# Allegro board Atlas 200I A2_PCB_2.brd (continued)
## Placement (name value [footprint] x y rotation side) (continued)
C3530  1nF  [SC0402-PA]  32.51 112.27 0 top
C3531  1nF  [SC0402-PA]  32.51 111.25 0 top
C3532  1nF  [SC0402-PA]  32.51 109.22 0 top
C3601  10nF  [SC0402-PB]  54.48 16.13 0 top
C3602  10nF  [SC0402-PB]  51.56 16.13 180 top
C3603  10nF  [SC0402-PB]  43.49 6.98 270 top
C3604  100nF  [SC0402-PB]  54.1 22.73 180 top
C3605  100nF  [SC0402-PB]  50.8 22.73 180 top
C3606  100nF  [SC0603-TC]  62.48 6.73 180 top
C3607  100nF  [SC0603-TC]  70.87 8.64 90 top
C3610  1nF  [SC0402-PA]  73.2 11.61 270 top
C3611  10nF  [SC0402-PB]  60.96 16.13 0 top
C3612  10nF  [SC0402-PB]  58.04 16.13 180 top
C3613  10nF  [SC0402-PB]  53.09 6.73 270 top
C3614  100nF  [SC0402-PB]  61.6 22.86 180 top
C3615  100nF  [SC0402-PB]  57.91 22.86 180 top
C3616  100nF  [SC0402-PB]  37.94 19.67 90 top
C3617  100nF  [SC0402-PB]  18.42 27.18 0 top
D1  LED  [HSD0603-LED]  134.57 84.58 180 top
D2  D2-3_D  [SOT23]  25.91 141.33 90 top
D3  D2-3_D*  [SOT23]  11.38 157.73 0 top
D4  DZ_A  [HSOD523]  168.45 84.96 90 top
D5  D_A  [SD2211]  32.43 167.94 90 top
D6  NONE  [SD3-2618C]  42.01 86.96 90 top
D7  D2-3_D  [SOT23]  146.05 9.91 180 top
D8  D2-3_D  [SOT23]  218.14 169.67 0 top
D9  D2-3_D  [SOT23]  163.2 21.08 270 top
D10  NONE  [SOP8-50-173]  144.76 170.07 180 top
D11  NONE  [SOP8-50-173]  162.18 170.07 0 top
D12  NONE  [SOP8-50-173]  174.65 169 0 top
D13  NONE  [SOP8-50-173]  206.11 170.37 0 top
D14  NONE  [SOP8-50-173]  224.27 170.37 180 top
D15  SCHOKITTY-041-70V  [SOT23]  61.77 38.99 180 top
D16  D2-3_D  [SOT23D]  210.74 195.58 180 top
D17  D2-3_D  [SOT23D]  214.12 195.58 180 top
D18  D_A  [SD1107S]  73.69 15.12 180 top
D19  D_A  [SD1107S]  73.69 17.4 180 top
D701  LED  [HSD0603-LED]  4.47 147.19 90 top
D801  LED  [HSD0603-LED]  194.03 80.04 180 top
D1101  D_A  [SD1107S]  229.24 49.4 270 top
D1102  D_A  [SD1107S]  229.24 42.54 270 top
D1501  NONE  [SOP8-50-173]  212.36 170.37 180 top
D1502  NONE  [SOP8-50-173]  180.36 169 180 top
D1503  NONE  [SOP8-50-173]  168.26 170.07 180 top
D1504  NONE  [SOP8-50-173]  151.01 170.07 180 top
D1601  NONE  [SOP8-50-173]  230.89 170.37 180 top
D1701  NONE  [SOT23]  67.44 162.88 0 top
D1702  NONE  [SOT23]  86.44 199.41 180 top
D1703  NONE  [SD1814C]  44.96 179.96 270 top
D1704  NONE  [SD1814C]  40.51 179.96 270 top
D1705  NONE  [SD1814C]  49.4 179.96 270 top
D1706  NONE  [SD1814C]  53.85 180.01 270 top
D1707  NONE  [SD1814C]  67.18 180.01 270 top
D1708  NONE  [SD1814C]  71.63 180.01 270 top
D1709  NONE  [SD1814C]  58.29 180.01 270 top
D1710  NONE  [SD1814C]  62.74 180.01 270 top
D1711  NONE  [SD1814C]  74.35 186.56 0 top
D1712  NONE  [SD1814C]  67.18 194.58 90 top
D1713  NONE  [SD1814C]  62.74 194.58 90 top
D1714  NONE  [SD1814C]  76.07 180.01 270 top
D1715  NONE  [SD1814C]  62.74 187.19 90 top
D1716  NONE  [SD1814C]  58.29 194.58 90 top
D1717  NONE  [SD1814C]  53.85 194.58 90 top
D1718  NONE  [SD1814C]  58.29 187.19 90 top
D1719  NONE  [SD1814C]  49.4 194.58 90 top
D1720  NONE  [SD1814C]  49.4 187.19 90 top
D1721  NONE  [SD1814C]  53.85 187.19 90 top
D1722  NONE  [SD1814C]  42.49 186.36 0 top
D1723  NONE  [SOT23]  53.47 162.88 0 top
D1724  NONE  [SOT23]  44.07 162.88 0 top
D1725  NONE  [SOT23]  60.58 162.88 0 top
D2201  NONE  [MLF10B-050-0301L]  207.03 154 90 top
D2202  NONE  [MLF10B-050-0301L]  156.34 18.57 270 top
D2203  NONE  [MLF10B-050-0301L]  167.56 19.45 180 top
D2303  NONE  [MLF10B-050-0301L]  102.57 198.35 180 top
D2305  NONE  [MLF10B-050-0301L]  107.52 198.35 180 top
D2307  NONE  [SOT23]  124.71 198.7 180 top
D2403  NONE  [MLF10B-050-0301L]  90.3 199.85 180 top
D2405  NONE  [MLF10B-050-0301L]  93.55 199.85 180 top
D2407  NONE  [SOT23]  97.66 192.02 90 top
D2408  NONE  [SOT23]  108.94 188.39 90 top
D2501  D2-3_D  [SOT23]  201.5 16.87 270 top
D2502  D2-3_D  [SOT23]  192.25 16.67 0 top
D2503  D2-3_D  [SOT23]  205.97 16.64 270 top
D2504  D2-3_D  [SOT23]  213.13 16 180 top
D3001  NONE  [SD1710A]  14.05 188.92 0 top
D3301  D2-3_D  [SOT23]  185.8 28.57 180 top
D3302  D2-3_D  [SOT23D]  223.65 22.99 270 top
D3401  D_A  [SD1107S]  9.98 47.5 270 top
D3402  NONE  [SD1814C]  44.96 18.54 0 top
D3501  NONE  [SD3-2618C]  36.2 134.24 180 top
D3502  NONE  [SD3-2618C]  28.7 111.23 180 top
D3601  NONE  [SD1814C]  31.88 18.8 180 top
D3602  NONE  [SD1814C]  24.69 18.8 0 top
F1001  NONE  [SF2-0302A]  188.1 56.83 90 top
F3001  NONE  [SF6127]  21.44 189.08 180 top
F3002  NONE  [SF2-0302A]  17.15 161.54 180 top
F3301  NONE  [SF6127]  185.17 35.13 270 top
F3302  NONE  [SF6127]  212.34 25.78 0 top
F3501  NONE  [SF6127]  34.67 154.43 0 top
F3502  NONE  [SF6127]  31.27 142.01 270 top
ICT1  NONE  [HOLE125]  5.44 71.14 0 top
ICT2  NONE  [HOLE125]  225.53 144.98 0 top
ID1  NONE  [ID-BOARD]  7.37 40.54 180 bottom
ID2  NONE  [ID-BOARD]  2.21 193.88 0 top
ID3  NONE  [ID-BOARD]  237.49 8.25 180 bottom
ID4  NONE  [ID-BOARD]  226.14 156.31 0 top
ID5  NONE  [ID-BOARD]  237.49 8.25 0 top
ID6  NONE  [ID-BOARD]  226.16 156.31 180 bottom
ID7  NONE  [ID-BOARD]  5.72 65.79 0 top
ID8  NONE  [ID-BOARD]  4.27 193.6 180 bottom
J1  NONE  [COPPER0201]  168.82 61.29 180 top
J2  NONE  [PPWC0304-RF]  12.7 200.58 180 top
J3  NONE  [SDIM02161-20B]  88.6 121.95 0 top
J4  NONE  [MOUNT3-2009F]  221.05 12.5 270 top
J5  NONE  [MOUNT3-2009F]  239.25 198.9 90 top
J7  NONE  [MOUNT3-2009F]  4.25 12.5 270 top
J8  NONE  [MB1-1612]  16.77 63.25 90 top
J9  NONE  [MB1-1612]  16.77 101.25 90 top
J601  NONE  [CARD75-2207]  16.76 149.35 0 top
J701  NONE  [SDIM0226-32]  150.75 92 0 top
J702  NONE  [SSIM0107-50-1927]  101.55 15.6 0 top
J803  NONE  [CARD75-2208B]  183.28 91.87 180 top
J901  NONE  [PIDC36-DRF-C]  243.05 14.87 90 top
J902  NONE  [RWBC0202-165R-A]  242.73 32.1 90 top
J903  NONE  [PMR0203-165RQ-A]  238.61 49.1 90 top
J1501  NONE  [MJ2-0102SRL-A]  158.11 203.35 180 top
J1502  NONE  [MJ2-0102SRL-A]  193.12 203.35 180 top
J1601  NONE  [MJ2-0102SRL-A]  228.12 203.35 180 top
J1701  NONE  [TB14-138S]  58.34 206.15 180 top
J1702  NONE  [TB10-138S-A]  78.16 206.15 180 top
J1901  NONE  [HSDC10-1614B]  123.08 11 0 top
J2001  NONE  [COPPER0201]  176.1 65.99 180 top
J2201  NONE  [RUSB9-200-1417A]  178.5 6.73 0 top
J2202  NONE  [RUSB9-200-1417A]  157.5 6.73 0 top
J2203  NONE  [RUSB9-180-0726J]  217.64 151.83 0 top
J2301  NONE  [RUSB19-050-1512]  117.95 208.6 180 top
J2401  NONE  [RUSB19-050-1512]  93.75 208.61 180 top
J2501  NONE  [VAF6-1406E]  195.7 4.15 90 top
J2502  NONE  [VAF6-1406E]  208.7 4.15 90 top
J2701  NONE  [SED40-32M-H]  34.39 34.59 0 top
JP960  *  [RHOLE168-T244B188]  183.28 143.65 0 top
K1701  NONE  [SRLY8-87-224]  67.92 170.61 90 top
K1702  NONE  [SRLY8-87-224]  48.66 170.61 90 top
K1703  NONE  [SRLY8-87-224]  38.78 170.61 90 top
K1704  NONE  [SRLY8-87-224]  58.29 170.61 90 top
L1001  110nH  [SL0806B]  186.84 70.81 270 top
L1201  2.2uH  [SL0806A]  145.01 65.43 180 top
L1401  1uH  [SL1008H]  102.77 149.55 90 top
L2001  4.7uH*  [SPL0302E]  131.95 35.13 270 top
L2101  4.7uH  [SPL0302E]  124.74 39.04 270 top
L3001  1uH  [SPL0707N]  8.76 163.7 0 top
L3101  1uH  [SPL0707N]  99.85 156.57 180 top
L3102  2.2uH  [SPL0404L]  98.98 176.2 270 top
L3103  2.2uH  [SPL0404L]  116.87 173.94 0 top
L3104  110nH  [SL0806B]  105.58 182.45 0 top
LB1  NONE  [SL0402C]  204.22 30.73 270 top
LB2  NONE  [SL0402C]  137.67 184.78 90 top
LB3  NONE  [SL0402C]  21.61 117.38 0 top
LB4  NONE  [SL0402C]  9.87 115.53 90 top
LB5  NONE  [SL0402C]  20.77 138.97 90 top
LB6  NONE  [SL0402C]  20.18 137.64 180 top
LB7  NONE  [SL0402C]  16.32 116.33 90 top
LB8  NONE  [SL0402C]  92.96 154.94 90 top
LB9  *  [SL0402C]  90.68 154.94 90 top
LB10  NONE  [SL0402C]  93.98 167 180 top
LB401  NONE  [SL0402C]  14.03 138.44 0 top
LB402  NONE  [SL0402C]  4.52 115.23 180 top
LB403  NONE  [SL0402C]  18.86 116.84 180 top
LB404  NONE  [SL0402C]  8.16 113.31 90 top
LB405  NONE  [SL0402C]  10.77 140.29 0 top
LB406  NONE  [SL0402C]  10.77 139.15 0 top
LB702  NONE  [SL0805]  157.02 77.14 0 top
LB703  NONE  [SL0805]  157.02 78.71 0 top
LB802  *  [SL0402C]  182.4 77.77 90 top
LB1202  NONE  [SL0402C]  142.9 63.45 270 top
LB1203  NONE  [SL0402C]  154.84 68.33 90 top
LB1401  NONE  [SL0402C]  104.8 145.69 180 top
LB1402  NONE  [SL0402C]  109.45 153.87 90 top
LB1403  NONE  [SL0402C]  110.74 155.98 0 top
LB1404  NONE  [SL0402C]  106.53 156.34 270 top
LB1405  NONE  [SL0402C]  110.26 151.71 0 top
LB1406  NONE  [SL0402C]  117.27 134.13 90 top
LB1407  NONE  [SL0402C]  109.14 143.85 0 top
LB1601  NONE  [SL0805-TD]  75.03 170.08 90 top
LB1602  NONE  [SL0805-TD]  76.78 170.08 90 top
LB1603  NONE  [SL0805]  216.92 183.46 90 top
LB1604  NONE  [SL0805]  218.49 183.46 90 top
LB1605  NONE  [SL0805]  80.02 170.08 90 top
LB1606  NONE  [SL0805]  78.44 170.08 90 top
LB1607  NONE  [SL0805]  83.17 170.08 90 top
LB1608  NONE  [SL0805]  81.59 170.08 90 top
LB1610  NONE  [SL0805]  187.12 159.46 180 top
LB1701  NONE  [SL0805]  70.99 162.56 180 top
LB1702  NONE  [SL0805]  83.46 198.25 270 top
LB1703  NONE  [SL0805]  57.02 162.56 180 top
LB1704  NONE  [SL0805]  47.24 161.8 90 top
LB1705  NONE  [SL0805]  64.01 162.56 180 top
LB2001  *  [SL0805]  145.42 54.99 270 top
LB2002  *  [SL0402C]  131.32 49.17 180 top
LB2101  NONE  [SL0805]  109.47 33.65 0 top
LB2201  NONE  [SL0402C]  155.4 30.4 0 top
LB2202  NONE  [SL0402C]  141.84 24.41 270 top
LB2203  NONE  [SL0402C]  234.09 174.09 270 top
LB2501  *  [SL0805]  188.85 4.83 0 top
LB2502  NONE  [SL0805]  200.14 13.24 90 top
LB2503  NONE  [SL0805]  192.41 13.73 0 top
LB2504  NONE  [SL0805]  187.58 2.41 180 top
LB2505  NONE  [SL0805]  192.08 24.21 180 top
LB2506  *  [SL0805]  209.17 12.57 180 top
LB2507  NONE  [SL0805]  212.42 12.57 0 top
LB2508  NONE  [SL0805]  203.96 13.59 180 top
LB2509  NONE  [SL0805]  214.91 12.52 90 top
LB2801  NONE  [SL0402C]  205.74 30.35 0 top
LB3001  NONE  [SL0402C]  8 138.58 0 top
LB3601  NONE  [SL0805]  43.15 10.16 90 top
LB3602  NONE  [SL0805]  62.48 8.89 90 top
LB3603  NONE  [SL0805]  53.09 9.78 90 top
LED3601  NONE  [SDA4-0606]  66.9 6.96 0 top
LED3602  NONE  [SDA4-0606]  46.89 6.96 0 top
LED3603  NONE  [SDA4-0606]  56.9 6.96 0 top
M1  NONE  [HOLE138-M3]  33.5 56.3 0 top
M2  NONE  [HOLE138-M3]  67 29.55 0 top
M3  NONE  [HOLE138-M3]  213.6 33.9 0 top
M4  NONE  [HOLE138-M3]  176 78.3 0 top
M5  NONE  [HOLE138-M3]  115 194.8 0 top
M6  NONE  [HOLE138-M3]  31 184 0 top
M7  NONE  [HOLE138-M3]  193.68 189.04 0 top
M8  NONE  [WSA1-1405]  192.7 170.8 0 top
M9  NONE  [WSA1-1405]  129.9 177.7 0 top
M10  NONE  [RHOLE168-T244B188B]  51.6 34.6 0 top
M11  NONE  [RHOLE168-T244B188B]  17.2 34.6 0 top
M12  NONE  [HOLE168-T244B188]  34.4 43.9 0 top
M13  none  [HOLE130]  200.5 32 0 top
M14  none  [HOLE138E]  21.7 170.8 0 top
M15  NONE  [HOLE138-M3]  150.75 119.65 0 top
M16  NONE  [HOLE197-315]  138.65 140.05 0 top
M17  NONE  [HOLE197-315]  162.85 140.05 0 top
M18  NONE  [HOLE78]  33.4 205 0 top
M19  NONE  [RHOLE189-254]  126.35 110.3 0 top
M20  NONE  [RHOLE189-254]  50.85 110.3 0 top
M21  NONE  [RHOLE189-254]  50.85 66.3 0 top
M22  NONE  [RHOLE189-254]  126.35 66.3 0 top
M23  NONE  [HOLE138-M3]  75.4 196.25 0 top
M24  NONE  [HOLE138-M3]  40.6 196.25 0 top
M25  NONE  [HOLE78]  82.6 208.02 0 top
M26  NONE  [HOLE177]  85.59 107.57 0 top
M27  NONE  [HOLE138-M3]  181.4 104.65 0 top
M28  NONE  [HOLE138-M3]  181.4 132.65 0 top
M3601  NONE  [LG2-1705]  66.9 12.4 270 top
M3602  NONE  [LG2-1705]  46.9 12.4 270 top
M3603  NONE  [LG2-1705]  56.9 12.4 270 top
NOREF  -  []  -254 -254 0 top
NOREF#2  -  [unnamed#2]  100.85 88.3 270 top
NOREF#3  -  [unnamed#2]  242.96 53.96 180 top
NOREF#4  -  []  49.35 72.21 0 top
NOREF#5  -  [unnamed#2]  201.4 129.26 90 top
NOREF#6  -  []  119.38 297.52 0 top
NOREF#7  -  []  66.42 0 90 top
NOREF#8  -  []  -254 -254 0 top
NOREF#9  -  []  -254 -254 0 top
NOREF#10  -  []  83.44 17.4 270 top
NOREF#11  -  []  151.11 160.93 0 top
NOREF#12  -  []  -254 -254 0 top
NOREF#13  -  [unnamed#2]  75.1 103.3 180 top
NOREF#14  -  []  84.71 368.13 0 top
NOREF#15  -  [unnamed#2]  231.5 151.15 90 top
NOREF#16  -  [unnamed#2]  201.4 87.14 90 top
NOREF#17  -  []  166.32 150.57 0 top
NOREF#18  -  []  246.38 7.62 0 top
NOREF#19  -  [unnamed#2]  75.1 73.3 180 top
NOREF#20  -  []  -254 -254 0 top
NOREF#21  -  [unnamed#2]  214.39 61.26 180 top
NOREF#22  -  [unnamed#2]  49.35 88.3 270 top
NOREF#23  -  []  3.23 82.37 0 top
NOREF#24  -  []  0 199.38 0 top
NOREF#25  -  []  7.09 81.94 90 top
NOREF#26  -  []  13.67 68.78 0 top
NOREF#27  -  []  -104.14 -189.23 0 top
NOREF#28  -  []  238.76 189.23 0 top
NOREF#29  -  []  137.57 164.76 0 top
NOREF#30  -  [unnamed#2]  241.92 181.48 90 top
NOREF#31  -  []  13.67 108 0 top
NOREF#32  -  []  5.31 21.89 0 top
Q1  FETN-GSD*  [SOT23]  76.71 130.49 270 top
Q2  FETN-GSD  [SOT23]  65.18 20.07 180 top
Q3  PMOS-GSD  [SOT23-3]  59.41 27.73 180 top
Q4  FETN-GSD  [SOT23]  10.67 26.92 0 top
Q701  FETN-GSD  [SOT523-3A]  189.84 67.79 90 top
Q702  NPN-BEC  [SOT23]  190.34 62.79 0 top
Q801  NPN-BEC  [SOT23]  189.15 76.02 90 top
Q1001  FETN-GSD  [SOT523-3A]  173.74 57.68 180 top
Q1002  FETN-GSD  [SOT523-3A]  176.28 54.97 270 top
Q1003  NPN-BEC  [SOT23]  166.7 72.34 0 top
Q1004  FETN-GSD  [SOT523-3A]  171.32 72.34 0 top
Q1101  MOS_SGD  [RF8-FSC-FDMS86181]  223.67 51.05 0 top
Q1102  MOS_SGD  [RF8-FSC-FDMS86181]  216.31 43.31 0 top
Q1103  MOS_SGD  [RF8-FSC-FDMS86181]  216.31 51.05 0 top
Q1104  MOS_SGD  [RF8-FSC-FDMS86181]  223.67 43.31 0 top
Q1105  FETN-GSD  [SOT523-3A]  223.01 56.51 90 top
Q1106  FETN-GSD  [SOT523-3A]  211.2 55.12 270 top
Q1107  NPN-BEC  [SOT23]  213.87 56.51 90 top
Q1701  NPN-BEC  [SOT23]  67.44 158.75 0 top
Q1702  NPN-BEC  [SOT23]  49.89 162.88 0 top
Q1703  NPN-BEC  [SOT23]  40.51 162.88 0 top
Q1704  NPN-BEC  [SOT23]  60.58 158.95 0 top
Q1801  PMOS-GSD  [SOT23-3]  33.78 159.26 270 top
Q1802  PMOS-GSD  [SOT23-3]  36.32 162.43 270 top
Q1803  NPN-BEC  [SOT23]  25.5 157.99 270 top
Q1804  NPN-BEC  [SOT23]  30.15 161.47 270 top
Q1901  PMOS-GSD  [SOT23-3]  132.19 13.19 90 top
Q1902  NPN-BEC  [SOT23]  133.95 6.38 90 top
Q2101  FETN-GSD  [SOT523-3A]  58.98 40.28 0 top
Q2901  NPN-BEC  [SOT23]  25.53 134.06 270 top
Q3001  MOS_SGD  [RF8-NXP-PSMN1R0]  10.41 176.78 0 top
Q3101  FETN-GSD  [SOT523-3A]  154 64.74 270 top
Q3102  PMOS-SGD  [RF8-TOS-TPCC8105]  152.25 58.24 180 top
Q3103  FETN-GSD  [SOT523-3A]  111.3 175.49 90 top
Q3104  FETN-GSD  [SOT523-3A]  112.81 187.67 90 top
Q3105  NPN-BEC  [SOT23]  109.42 169.44 90 top
Q3106  NPN-BEC  [SOT23]  116.21 184.28 90 top
Q3201  FETN-GSD  [SOT523-3A]  157.66 61.77 180 top
Q3202  PMOS-SGD  [RF8-TOS-TPCC8105]  157.42 55.9 180 top
Q3301  PMOS-SGD  [SOT-PPAK-8-0303G]  218.97 24.36 270 top
Q3302  FETN-GSD  [SOT523-3A]  213.74 20.19 270 top
Q3303  PMOS-SGD  [SOT-PPAK-8-0303G]  181.99 28.63 180 top
Q3304  NPN-BEC  [SOT23]  178.82 36.78 270 top
Q3401  NPN-BEC  [SOT23]  17.45 83.9 180 top
Q3402  NPN-BEC  [SOT23]  21.06 83.9 180 top
Q3501  PMOS-SGD  [SOT-PPAK-8-0303G]  37.23 148.3 180 top
Q3502  NPN-BEC  [SOT23]  32.06 148.21 270 top
Q3503  NPN-BEC  [SOT23]  25.53 137.69 270 top
Q3504  PMOS-SGD  [RF8-TOS-TPCC8105]  31.52 134.17 180 top
Q3601  NPN-BEC  [SOT23]  53.98 20.07 180 top
Q3602  NPN-BEC  [SOT23]  50.29 20.07 180 top
Q3604  NPN-BEC  [SOT23]  75.77 11.91 270 top
Q3605  NPN-BEC  [SOT23]  61.21 20.07 180 top
Q3606  NPN-BEC  [SOT23]  57.66 20.07 180 top
R1  2k  [SR0402-TA]  154.83 57.51 270 top
R2  4.7k  [SR0402-TA]  205.74 29.21 180 top
R3  4.7k  [SR0402-TA]  189.99 51.05 270 top
R4  4.7k*  [SR0402-TA]  194.31 38.35 270 top
R5  4.7k*  [SR0402-TA]  195.96 56.51 90 top
R6  4.7k  [SR0402-TA]  212.34 45.08 0 top
R7  4.7k  [SR0402-TA]  212.34 43.31 0 top
R8  4.7k  [SR0402-TA]  212.34 44.2 0 top
R9  4.7k  [SR0402-TA]  212.34 41.4 0 top
R10  1k  [SR0402-TA]  197.99 56.51 90 top
R11  1k  [SR0402-TA]  210.19 51.94 90 top
R12  1k  [SR0402-TA]  212.34 42.29 0 top
R13  1k  [SR0402-TA]  208.66 51.94 0 top
R14  100  [SR0402-TA]  208.92 50.11 180 top
R15  100  [SR0402-TA]  208.31 46.91 90 top
R16  1k*  [SR0402-TA]  196.98 56.51 270 top
R17  1M*  [SR0402-TA]  208.31 48.56 90 top
R18  0*  [SR0402-TA]  201.55 38.63 270 top
R19  2.2*  [SR0805-TB]  170.99 58.86 0 top
R20  1k  [SR0402-TA]  192.91 39.75 0 top
R21  4.7k  [SR0402-TA]  122.52 27.36 180 top
R22  4.7k*  [SR0402-TA]  120.29 28.71 270 top
R23  4.7k  [SR0402-TA]  119.57 25.72 0 top
R24  1k*  [SR0402-TA]  120 26.96 90 top
R25  4.7k  [SR0402-TA]  188.34 38.86 0 top
R26  4.7k  [SR0402-TA]  190.75 49.4 180 top
R27  4.7k  [SR0402-TA]  190.63 43.81 0 top
R28  4.7k  [SR0402-TA]  190.63 44.78 0 top
R29  33  [SR0402-TA]  192.41 36.32 0 top
R30  240  [SR0402-TA]  134.24 85.72 180 top
R31  0  [SR0402-TA]  88.15 169 180 top
R32  0  [SR0402-TA]  145.67 83.06 270 top
R33  4.7k  [SR0402-TA]  64.55 154.69 270 top
R34  4.7k  [SR0402-TA]  79.25 150.75 0 top
R35  4.7k  [SR0402-TA]  190.12 46.02 90 top
R36  4.7k  [SR0402-TA]  183.9 40.39 90 top
R37  4.7k  [SR0402-TA]  188.34 41.78 180 top
R38  4.7k  [SR0402-TA]  188.34 39.75 180 top
R39  4.7k  [SR0402-TA]  66.75 141.1 90 top
R40  4.7k  [SR0402-TA]  67.64 141.1 90 top
R41  4.7k  [SR0402-TA]  68.53 141.1 90 top
R42  4.7k  [SR0402-TA]  79.09 141.45 90 top
R43  4.7k  [SR0402-TA]  80.43 141.45 90 top
R44  4.7k  [SR0402-TA]  81.28 141.45 90 top
R45  4.7k  [SR0402-TA]  82.3 141.58 90 top
R46  4.7k  [SR0402-TA]  83.31 141.58 90 top
R47  4.7k  [SR0402-TA]  84.33 141.58 90 top
R48  0  [SR0402-TA]  146.69 83.06 270 top
R49  0  [SR0402-TA]  172.44 85.06 270 top
R50  0  [SR0402-TA]  171.44 85.06 270 top
R51  1k*  [SR0402-TA]  178.89 55.18 180 top
R52  0*  [SR0402-TA]  134.44 95.12 90 top
R53  0*  [SR0402-TA]  134.44 93.34 270 top
R54  4.7k*  [SR0402-TA]  178.89 54.18 0 top
R55  1k*  [SR0402-TA]  4.45 151.26 180 top
R56  33  [SR0402-TA]  12.45 154.81 90 top
R57  33  [SR0402-TA]  4.45 152.4 180 top
R58  33  [SR0402-TA]  176.4 53.47 180 top
R59  0  [SR0402-TA]  147.7 64.39 0 top
R60  33  [SR0402-TA]  139.12 82.6 180 top
R61  1k  [SR0402-TA]  200.53 38.61 270 top
R62  1k  [SR0402-TA]  122.52 29.07 0 top
R63  100  [SR0402-TA]  122.48 24.49 0 top
R64  301  [SR0402-TA]  122.5 25.54 0 top
R65  0  [SR0402-TA]  186.44 47.47 0 top
R66  0  [SR0402-TA]  208.41 38.61 90 top
R67  33  [SR0402-TA]  166.42 42.93 0 top
R68  33  [SR0402-TA]  158.22 43.95 0 top
R69  33  [SR0402-TA]  159.23 52.96 0 top
R70  33  [SR0402-TA]  159.06 37.2 0 top
R71  33  [SR0402-TA]  159.06 38.18 0 top
R72  33  [SR0402-TA]  35.1 24.79 180 top
R73  33  [SR0402-TA]  177.22 40.49 270 top
R74  2.2*  [SR0805-TB]  173.1 68.94 270 top
R75  2k  [SR0402-TA]  179.48 29.11 270 top
R76  33  [SR0402-TA]  194.95 36.32 90 top
R77  33  [SR0402-TA]  123.38 23.09 90 top
R78  4.7k  [SR0402-TA]  94.64 185.91 180 top
R79  4.7k  [SR0402-TA]  94.64 192.16 180 top
R80  4.7k  [SR0402-TA]  94.64 181.24 180 top
R81  4.7k  [SR0402-TA]  94.64 176.03 180 top
R82  33  [SR0402-TA]  137.24 82.6 180 top
R83  1k*  [SR0402-TA]  83.49 131.1 270 top
R84  1k*  [SR0402-TA]  184.55 53.74 270 top
R85  1k*  [SR0402-TA]  183.64 53.74 270 top
R86  10  [SR0402-TA]  27.76 175.97 90 top
R87  0  [SR0402-TA]  88.15 169.91 180 top
R88  0  [SR0402-TA]  59.05 42.45 0 top
R89  4.7k*  [SR0402-TA]  27.43 144.32 90 top
R90  4.7k  [SR0402-TA]  5.71 98.71 270 top
R91  4.7k  [SR0402-TA]  4.82 98.71 270 top
R92  4.7k  [SR0402-TA]  8.13 110.62 180 top
R93  4.7k  [SR0402-TA]  4.07 109.93 90 top
R94  0  [SR0402-TA]  43.05 27.43 270 top
R95  0  [SR0402-TA]  42.04 27.43 270 top
R96  4.7k  [SR0402-TA]  188.34 43.81 0 top
R97  4.7k  [SR0402-TA]  186.41 40.74 270 top
R98  4.7k  [SR0402-TA]  190.63 42.8 180 top
R99  4.7k  [SR0402-TA]  188.34 40.77 180 top
R100  100*  [SR0402-TA]  143.31 85.67 180 top
R101  33  [SR0402-TA]  159.41 85.5 90 top
R102  33  [SR0402-TA]  160.32 85.5 90 top
R103  33  [SR0402-TA]  159.06 40.38 0 top
R104  1k  [SR0402-TA]  97.03 30.35 0 top
R105  33  [SR0402-TA]  161.22 85.5 90 top
R106  33  [SR0402-TA]  162.13 85.5 90 top
R107  4.7k  [SR0402-TA]  165.02 44.22 90 top
R108  4.7k*  [SR0402-TA]  160 44.2 90 top
R109  1k*  [SR0402-TA]  98.83 49.12 90 top
R110  1k*  [SR0402-TA]  100.62 49.12 90 top
R111  1k*  [SR0402-TA]  99.71 50.9 270 top
R112  1k*  [SR0402-TA]  98.86 50.9 270 top
R113  100  [SR0402-TA]  192.99 157.05 0 top
R114  33  [SR0402-TA]  49.98 142.71 90 top
R115  33  [SR0402-TA]  159.23 48.73 0 top
R116  33  [SR0402-TA]  159.23 47.72 0 top
R117  4.7k  [SR0402-TA]  195.73 92.1 180 top
R118  4.7k  [SR0402-TA]  129.51 137.42 270 top
R119  33  [SR0402-TA]  159.23 46.61 0 top
R120  0  [SR0402-TA]  190.97 46.02 270 top
R121  1k*  [SR0402-TA]  131.57 137.42 90 top
R122  33  [SR0402-TA]  159.23 45.55 0 top
R123  0  [SR0402-TA]  184.91 40.39 270 top
R124  33  [SR0402-TA]  166.7 48.41 0 top
R125  0  [SR0402-TA]  175.44 37.31 0 top
R126  0  [SR0402-TA]  175.44 36.42 0 top
R127  1k*  [SR0402-TA]  153.54 67.33 180 top
R128  1k*  [SR0402-TA]  116.38 178.18 0 top
R129  1k*  [SR0402-TA]  103.4 174.55 270 top
R130  1k*  [SR0402-TA]  14.57 157.5 90 top
R131  1k*  [SR0402-TA]  28.62 148.84 90 top
R132  2.2*  [SR0805-TB]  29.97 175.89 180 top
R133  33  [SR0402-TA]  112.34 185.62 270 top
R134  33  [SR0402-TA]  109.18 175.95 90 top
R135  1k  [SR0402-TA]  71.48 11.61 90 top
R136  2.2  [SR0402-TB]  106.29 195.12 90 top
R137  1k*  [SR0402-TA]  131.49 46.48 0 top
R138  33  [SR0402-TA]  166.73 46.79 0 top
R139  33  [SR0402-TA]  166.73 45.79 0 top
R140  33  [SR0402-TA]  166.73 44.42 0 top
R141  4.7k  [SR0402-TA]  164.39 35.18 270 top
R142  10k  [SR0402-TA]  55.94 127.76 180 top
R143  4.7k*  [SR0402-TA]  157.12 36.04 0 top
R144  2.2  [SR0402-TB]  107.2 195.12 90 top
R145  33  [SR0402-TA]  159.23 49.78 0 top
R146  33  [SR0402-TA]  156.18 42.9 0 top
R147  33  [SR0402-TA]  159.23 50.84 0 top
R148  33  [SR0402-TA]  158.52 42.89 0 top
R149  1k  [SR0402-TA]  77.72 146.73 180 top
R150  1k  [SR0402-TA]  62.33 154.91 0 top
R151  1k  [SR0402-TA]  61.43 152.78 90 top
R152  1k  [SR0402-TA]  77.72 149.6 180 top
R153  1k  [SR0402-TA]  76.12 141.58 270 top
R154  1k  [SR0402-TA]  61.24 141.1 270 top
R155  1k  [SR0402-TA]  60.11 143.41 90 top
R156  1k  [SR0402-TA]  77.22 141.58 270 top
R157  33  [SR0402-TA]  159.23 51.9 0 top
R158  33  [SR0402-TA]  166.42 41.87 0 top
R159  33  [SR0402-TA]  166.73 49.72 0 top
R160  33  [SR0402-TA]  166.7 50.76 0 top
R161  33  [SR0402-TA]  166.7 51.79 0 top
R162  0  [SR0402-TA]  71.63 46.99 180 top
R163  0*  [SR0402-TA]  136.17 61.85 0 top
R164  33  [SR0402-TA]  166.7 52.82 0 top
R165  0  [SR0402-TA]  154.05 61.98 180 top
R166  33  [SR0402-TA]  166.42 39.81 0 top
R167  4.7k  [SR0402-TA]  24.36 26.92 180 top
R168  4.7k  [SR0402-TA]  13.59 26.54 270 top
R169  4.7k*  [SR0402-TA]  16.13 27.18 180 top
R170  33  [SR0402-TA]  35.1 25.85 180 top
R171  33  [SR0402-TA]  35.1 23.73 180 top
R172  0*  [SR0402-TA]  154.05 60.96 180 top
R173  33  [SR0402-TA]  35.1 22.67 180 top
R174  0*  [SR0402-TA]  14.61 26.54 270 top
R175  33  [SR0402-TA]  24.31 25.96 180 top
R176  0  [SR0402-TA]  107.19 31.94 270 top
R177  1k*  [SR0402-TA]  185.45 53.72 270 top
R178  100k*  [SR0402-TA]  150.76 65.91 90 top
R179  1k*  [SR0402-TA]  146.49 68.2 90 top
R180  33  [SR0402-TA]  24.31 23.84 180 top
R181  33  [SR0402-TA]  24.31 22.78 180 top
R182  4.7k*  [SR0402-TA]  22.23 22.78 0 top
R183  4.7k*  [SR0402-TA]  22.23 23.84 0 top
R184  4.7k  [SR0402-TA]  112.36 137.2 90 top
R185  4.7k  [SR0402-TA]  111.5 137.2 90 top
R186  0*  [SR0402-TA]  149.61 55.24 180 top
R187  10k  [SR0402-TA]  54.04 127.76 0 top
R188  120*  [SR0402-TA]  90.55 169.46 270 top
R189  33  [SR0402-TA]  121.81 39.29 90 top
R190  2.2  [SR0402-TB]  145.69 78.64 90 top
R191  2.2  [SR0402-TB]  142.75 78.64 90 top
R192  2.2  [SR0402-TB]  143.66 78.64 90 top
R193  2.2  [SR0402-TB]  140.47 78.64 90 top
R194  2.2  [SR0402-TB]  141.38 78.64 90 top
R195  2.2  [SR0402-TB]  147.74 78.59 90 top
R196  2.2  [SR0402-TB]  146.84 78.59 90 top
R197  2.2  [SR0402-TB]  148.98 147.64 0 top
R198  1k  [SR0402-TA]  26.82 126.24 180 top
R199  1k  [SR0402-TA]  26.82 127.25 180 top
R200  4.7k  [SR0402-TA]  33.53 28.57 180 top
R201  4.7k*  [SR0402-TA]  134.49 50.42 90 top
R202  33  [SR0402-TA]  107.19 131.98 180 top
R203  33  [SR0402-TA]  188.29 52.02 180 top
R204  4.7k  [SR0402-TA]  110.65 137.2 90 top
R205  33  [SR0402-TA]  166.42 40.82 0 top
R206  0*  [SR0402-TA]  90.69 49.19 270 top
R207  0*  [SR0402-TA]  90.69 50.82 90 top
R208  1k  [SR0402-TA]  39.02 128.02 270 top
R209  0*  [SR0402-TA]  57.28 27.94 270 top
R210  120*  [SR0402-TA]  101.54 196.52 0 top
R211  120*  [SR0402-TA]  104.25 196.44 0 top
R212  120*  [SR0402-TA]  106.74 196.44 0 top
R213  120*  [SR0402-TA]  108.39 193.09 0 top
R214  120*  [SR0402-TA]  91.85 197.74 0 top
R215  120*  [SR0402-TA]  94.72 197.03 0 top
R216  120*  [SR0402-TA]  97.31 197.03 0 top
R217  120*  [SR0402-TA]  89.41 197.74 0 top
R218  33  [SR0402-TA]  166.42 38.75 0 top
R219  33  [SR0402-TA]  24.31 24.9 180 top
R220  33  [SR0402-TA]  166.42 36.63 0 top
R221  0  [SR0402-TA]  89.41 50.85 0 top
R222  0  [SR0402-TA]  97.97 49.12 270 top
R223  0  [SR0402-TA]  97.97 50.9 90 top
R224  1M*  [SR0402-TA]  97.12 50.02 90 top
R225  0  [SR0402-TA]  186.69 50.42 270 top
R226  0  [SR0402-TA]  190.75 38.86 180 top
R227  4.7k  [SR0402-TA]  195.96 36.32 90 top
R228  4.7k  [SR0402-TA]  192.41 37.34 0 top
R229  0  [SR0402-TA]  132.78 45.72 90 top
R230  0  [SR0402-TA]  185.47 85.31 90 top
R231  0  [SR0402-TA]  186.38 85.31 90 top
R232  0  [SR0402-TA]  183.57 85.68 90 top
R233  0  [SR0402-TA]  184.48 85.68 90 top
R234  0*  [SR0402-TA]  25.53 80.14 90 top
R235  100k  [SR0402-TA]  27.81 80.14 270 top
R236  180  [SR0402-TA]  23.27 80.14 270 top
R237  33  [SR0402-TA]  166.42 35.58 0 top
R238  10k  [SR0402-TA]  69.47 43.43 180 top
R239  4.7k  [SR0402-TA]  10.35 133.05 270 top
R240  1k  [SR0402-TA]  7.8 134.46 270 top
R241  4.7k  [SR0402-TA]  9.49 133.05 270 top
R242  1k  [SR0402-TA]  6.95 134.46 270 top
R243  4.7k  [SR0402-TA]  7.04 121.59 0 top
R244  1k  [SR0402-TA]  4.9 121.59 0 top
R245  4.7k  [SR0402-TA]  11.2 133.05 270 top
R246  1k  [SR0402-TA]  8.66 134.46 270 top
R247  33  [SR0402-TA]  166.68 92.68 90 top
R248  10k*  [SR0402-TA]  61.6 24.89 180 top
R249  10k  [SR0402-TA]  59.56 30.66 180 top
R250  1k  [SR0402-TA]  68.2 20.07 180 top
R251  0  [SR0402-TA]  158.84 23.69 0 top
R252  0  [SR0402-TA]  158.84 22.78 0 top
R253  0  [SR0402-TA]  158.84 21.88 0 top
R254  0  [SR0402-TA]  158.84 20.97 0 top
R255  1k  [SR0402-TA]  68.2 22.28 180 top
R256  33  [SR0402-TA]  63.12 23.37 270 top
R257  4.7k  [SR0402-TA]  109.79 137.2 90 top
R258  4.7k  [SR0402-TA]  108.94 137.2 90 top
R259  33  [SR0402-TA]  183.64 51.63 270 top
R260  33  [SR0402-TA]  184.55 51.63 270 top
R261  33  [SR0402-TA]  185.45 51.63 270 top
R262  4.7k  [SR0402-TA]  5.1 133.14 270 top
R263  1K*  [SR0402-TA]  4.66 131.79 180 top
R264  1M*  [SR0402-TA]  7.89 126.58 0 top
R265  33  [SR0402-TA]  14.54 120.81 90 top
R266  33  [SR0402-TA]  7.04 122.61 0 top
R267  33  [SR0402-TA]  4.24 133.14 270 top
R268  0  [SR0402-TA]  192.76 52.31 0 top
R269  0  [SR0402-TA]  192.76 51.46 0 top
R270  0  [SR0402-TA]  193.17 56.51 270 top
R271  0  [SR0402-TA]  188.35 54.01 0 top
R272  0  [SR0402-TA]  188.35 53 0 top
R273  4.7k  [SR0402-TA]  107.44 137.2 90 top
R274  33  [SR0402-TA]  64.08 143.38 90 top
R275  33  [SR0402-TA]  64.55 152.78 90 top
R276  1k  [SR0402-TA]  65.63 152.78 90 top
R277  4.7k*  [SR0402-TA]  65.63 154.69 270 top
R278  4.7k*  [SR0402-TA]  65 141.1 90 top
R279  1k  [SR0402-TA]  64.14 141.1 270 top
R280  4.7k*  [SR0402-TA]  74.04 131.1 270 top
R281  0*  [SR0402-TA]  79.25 131.1 270 top
R282  4.7k*  [SR0402-TA]  81.28 131.1 90 top
R283  1k  [SR0402-TA]  168.38 38.74 180 top
R284  4.7k*  [SR0402-TA]  171.4 38.74 180 top
R285  4.7k*  [SR0402-TA]  22.23 24.9 0 top
R286  4.7k*  [SR0402-TA]  171.4 36.63 180 top
R287  4.7k*  [SR0402-TA]  22.23 25.96 0 top
R288  33*  [SR0402-TA]  159.06 39.32 0 top
R289  1k  [SR0402-TA]  168.38 36.63 180 top
R290  33*  [SR0402-TA]  166.42 37.69 0 top
R291  4.7k*  [SR0402-TA]  154.43 40.39 0 top
R292  1k  [SR0402-TA]  157.12 40.37 180 top
R293  4.7k*  [SR0402-TA]  154.43 37.22 0 top
R294  4.7k*  [SR0402-TA]  154.43 38.28 0 top
R295  4.7k*  [SR0402-TA]  37.19 25.85 180 top
R296  1k  [SR0402-TA]  157.12 37.19 180 top
R297  1k  [SR0402-TA]  157.12 38.25 180 top
R298  4.7k*  [SR0402-TA]  131.83 38.48 180 top
R299  2.2  [SR0402-TB]  103.8 195.12 90 top
R300  2.2  [SR0402-TB]  104.7 195.12 90 top
R301  0  [SR0402-TA]  7.89 127.45 0 top
R302  33  [SR0402-TA]  10.98 120.81 90 top
R303  33  [SR0402-TA]  12 120.81 90 top
R304  0  [SR0402-TA]  7.04 120.57 0 top
R305  4.7k*  [SR0402-TA]  19.96 132.13 180 top
R306  1K  [SR0402-TA]  19.96 133.26 0 top
R307  4.7k*  [SR0402-TA]  25.41 118.45 180 top
R308  1K  [SR0402-TA]  25.41 117.59 0 top
R309  4.7k*  [SR0402-TA]  16.57 118.68 90 top
R310  1K  [SR0402-TA]  15.56 120.81 270 top
R311  1K  [SR0402-TA]  16.57 120.81 270 top
R312  1K  [SR0402-TA]  7.04 123.62 180 top
R313  1K  [SR0402-TA]  25.41 120.16 0 top
R314  4.7k*  [SR0402-TA]  9.97 118.68 90 top
R315  1K  [SR0402-TA]  13.55 118.68 270 top
R316  4.7k  [SR0402-TA]  21.3 128.41 180 top
R317  1K*  [SR0402-TA]  21.3 127.55 0 top
R318  4.7k*  [SR0402-TA]  14.54 118.68 90 top
R319  1K  [SR0402-TA]  9.97 120.81 90 top
R320  4.7k  [SR0402-TA]  4.9 120.57 0 top
R321  1K*  [SR0402-TA]  4.9 119.56 180 top
R322  4.7k  [SR0402-TA]  10.98 118.68 90 top
R323  1K*  [SR0402-TA]  12 118.68 270 top
R324  4.7k  [SR0402-TA]  7.66 131.87 270 top
R325  4.7k  [SR0402-TA]  6.81 131.87 270 top
R326  4.7k  [SR0402-TA]  5.95 131.87 270 top
R327  4.7k  [SR0402-TA]  19.96 131.28 180 top
R328  4.7k  [SR0402-TA]  15.56 118.68 90 top
R329  4.7k  [SR0402-TA]  4.9 122.61 0 top
R330  2.2  [SR0402-TB]  101.02 195.12 90 top
R331  2.2  [SR0402-TB]  101.93 195.12 90 top
R332  4.7k*  [SR0402-TA]  4.9 123.62 0 top
R333  4.7k*  [SR0402-TA]  25.41 119.3 180 top
R334  1k  [SR0402-TA]  168.5 48.42 180 top
R335  4.7k*  [SR0402-TA]  171.45 48.26 180 top
R336  4.7k*  [SR0402-TA]  132.78 43.69 270 top
R337  10k  [SR0402-TA]  110.41 36.78 90 top
R342  4.7k*  [SR0402-TA]  154.45 48.72 0 top
R343  1k  [SR0402-TA]  157.31 48.76 180 top
R344  4.7k*  [SR0402-TA]  154.45 45.55 0 top
R345  4.7k*  [SR0402-TA]  154.45 46.61 0 top
R346  4.7k*  [SR0402-TA]  154.45 47.66 0 top
R347  1k  [SR0402-TA]  157.31 44.97 180 top
R348  1k  [SR0402-TA]  157.31 46.23 180 top
R349  1k  [SR0402-TA]  157.31 47.47 180 top
R350  1k  [SR0402-TA]  168.53 49.73 180 top
R351  4.7k*  [SR0402-TA]  171.45 49.32 180 top
R352  4.7k*  [SR0402-TA]  154.45 49.78 0 top
R353  1k  [SR0402-TA]  157.31 49.79 180 top
R354  1k  [SR0402-TA]  168.5 51.8 180 top
R355  4.7k*  [SR0402-TA]  171.45 51.43 180 top
R356  4.7k*  [SR0402-TA]  171.45 50.38 180 top
R357  1k  [SR0402-TA]  168.5 50.76 180 top
R358  1k  [SR0402-TA]  168.5 52.83 180 top
R359  4.7k*  [SR0402-TA]  171.45 52.49 180 top
R360  4.7k*  [SR0402-TA]  154.45 51.9 0 top
R361  1k  [SR0402-TA]  157.31 51.88 180 top
R362  4.7k*  [SR0402-TA]  154.45 50.84 0 top
R363  1k  [SR0402-TA]  157.31 50.85 180 top
R364  4.7k*  [SR0402-TA]  154.45 52.95 0 top
R365  1k  [SR0402-TA]  157.31 52.94 180 top
R376  4.7k*  [SR0402-TA]  37.19 22.67 180 top
R377  4.7k*  [SR0402-TA]  37.19 23.73 180 top
R378  4.7k*  [SR0402-TA]  37.19 24.79 180 top
R388  1k*  [SR0402-TA]  168.38 37.68 180 top
R389  4.7k*  [SR0402-TA]  171.45 37.72 180 top
R390  4.7k*  [SR0402-TA]  154.43 39.32 0 top
R391  1k*  [SR0402-TA]  157.12 39.32 180 top
R392  2.2  [SR0402-TB]  107.89 191.64 90 top
R393  2.2  [SR0402-TB]  108.8 191.64 90 top
R394  2.2  [SR0402-TB]  94.23 195.73 90 top
R395  2.2  [SR0402-TB]  95.13 195.73 90 top
R396  2.2  [SR0402-TB]  91.43 195.73 90 top
R397  2.2  [SR0402-TB]  92.33 195.73 90 top
R398  2.2  [SR0402-TB]  89.16 195.73 90 top
R399  2.2  [SR0402-TB]  90.07 195.73 90 top
R400  2.2  [SR0402-TB]  96.8 195.73 90 top
R401  2.2  [SR0402-TB]  97.7 195.73 90 top
R402  1  [SR0402-TB]  108.71 128.55 90 top
R403  1  [SR0402-TB]  107.85 130.59 0 top
R404  1  [SR0402-TB]  106.12 130.71 90 top
R405  1  [SR0402-TB]  104.25 130.4 90 top
R406  1  [SR0402-TB]  103.34 130.4 90 top
R407  1  [SR0402-TB]  102.41 130.89 90 top
R408  1  [SR0402-TB]  95.97 130.17 0 top
R409  1  [SR0402-TB]  94.71 130.4 90 top
R410  1  [SR0402-TB]  93.8 130.4 90 top
R411  1  [SR0402-TB]  92.81 130.73 90 top
R412  1  [SR0402-TB]  91.86 130.05 90 top
R413  1  [SR0402-TB]  90.92 131.1 90 top
R414  4.7k  [SR0402-TA]  198.2 58.78 0 top
R602  4.7k*  [SR0402-TA]  4.45 150.24 180 top
R604  4.7k*  [SR0402-TA]  13.71 157.5 270 top
R606  330*  [SR0402-TA]  9.14 158.62 270 top
R611  240  [SR0402-TA]  4.45 149.23 180 top
R612  100*  [SR0402-TA]  21.21 154.43 0 top
R614  0  [SR0402-TA]  18.36 155.07 270 top
R615  0  [SR0402-TA]  19.3 155.07 270 top
R616  0  [SR0402-TA]  16.38 155.07 270 top
R617  0  [SR0402-TA]  15.44 155.07 270 top
R701  4.7k*  [SR0402-TA]  188.98 69.85 90 top
R702  1k  [SR0402-TA]  190.5 65.79 90 top
R704  33  [SR0402-TA]  143.31 82.65 180 top
R705  33  [SR0402-TA]  143.31 83.69 180 top
R706  33  [SR0402-TA]  138.38 85.32 270 top
R708  0  [SR0402-TA]  152.04 82.04 270 top
R709  0  [SR0402-TA]  152.96 82.04 270 top
R712  10k  [SR0402-TA]  191.52 65.79 270 top
R713  1k  [SR0402-TA]  191.05 59.84 90 top
R714  1k  [SR0402-TA]  190.19 59.84 90 top
R722  15k  [SR0402-TA]  96.97 32.96 180 top
R801  33  [SR0402-TA]  187.58 84.96 270 top
R802  33  [SR0402-TA]  189.99 84.96 270 top
R803  33  [SR0402-TA]  188.6 84.96 270 top
R805  100*  [SR0402-TA]  179.71 85.6 0 top
R806  0  [SR0402-TA]  186.38 82.17 90 top
R807  0  [SR0402-TA]  185.47 82.17 90 top
R821  1k  [SR0402-TA]  192.28 73.41 0 top
R822  2k  [SR0402-TA]  193.11 75.39 270 top
R829  10k  [SR0402-TA]  175.41 85.09 270 top
R830  10k  [SR0402-TA]  174.52 85.09 270 top
R831  4.7k*  [SR0402-TA]  193.43 78.85 0 top
R832  33  [SR0402-TA]  176.3 85.09 270 top
R833  33  [SR0402-TA]  173.66 85.09 270 top
R841  0  [SR0402-TA]  182.4 77.77 90 top
R848  240  [SR0402-TA]  191.89 79.55 90 top
R850  33  [SR0402-TA]  195.73 92.99 0 top
R851  10k  [SR0402-TA]  177.44 85.09 270 top
R852  33  [SR0402-TA]  178.33 85.09 270 top
R1001  20k  [SR0402-TA]  181.81 62.43 180 top
R1002  10  [SR0402-TA]  176.76 56.99 0 top
R1003  10*  [SR0402-TA]  176.76 58.8 0 top
R1004  240  [SR0402-TA]  176.76 57.84 180 top
R1005  1k*  [SR0402-TA]  179.03 57.71 90 top
R1006  1k  [SR0402-TA]  181.81 63.3 0 top
R1007  10k  [SR0402-TA]  175.01 68.12 0 top
R1008  33  [SR0402-TA]  173.81 54.84 180 top
R1009  1k  [SR0402-TA]  169.32 72.49 0 top
R1010  301  [SR0402-TA]  173.81 55.69 0 top
R1011  49.9  [SR0402-TA]  173.81 53.98 0 top
R1012  10k  [SR0402-TA]  169.32 73.7 180 top
R1013  1k  [SR0402-TA]  175.29 58.42 90 top
R1014  1k  [SR0402-TA]  175.29 56.77 270 top
R1015  1k  [SR0402-TA]  163.96 72.66 0 top
R1016  1k  [SR0402-TA]  163.96 73.67 180 top
R1017  10k  [SR0402-TA]  204.29 24.23 270 top
R1018  10k  [SR0402-TA]  203.78 21.82 180 top
R1019  240  [SR0402-TA]  202.01 21.01 180 top
R1020  3k  [SR0402-TA]  203.78 20.8 180 top
R1021  10k  [SR0402-TA]  203.28 24.23 90 top
R1022  33  [SR0402-TA]  177.66 51.63 90 top
R1023  33  [SR0402-TA]  179.69 51.63 90 top
R1024  33  [SR0402-TA]  178.67 51.63 90 top
R1025  33  [SR0402-TA]  181.72 51.63 90 top
R1026  33  [SR0402-TA]  180.7 51.63 90 top
R1027  33  [SR0402-TA]  182.74 51.63 90 top
R1028  33  [SR0402-TA]  173.35 46.97 180 top
R1029  33  [SR0402-TA]  183.64 49.02 90 top
R1030  4.7k  [SR0402-TA]  175.62 51.63 90 top
R1031  4.7k*  [SR0402-TA]  173.35 43.03 180 top
R1032  4.7k*  [SR0402-TA]  175.18 40.49 270 top
R1033  1k  [SR0402-TA]  176.2 40.49 90 top
R1034  1k  [SR0402-TA]  173.35 43.93 0 top
R1035  1k*  [SR0402-TA]  174.61 51.63 270 top
R1036  33  [SR0402-TA]  176.72 51.63 90 top
R1101  33  [SR0402-TA]  219.96 55.75 180 top
R1102  33  [SR0402-TA]  227.46 41.71 90 top
R1103  33  [SR0402-TA]  219.96 41.71 90 top
R1104  1k  [SR0402-TA]  225.93 56.77 180 top
R1105  1k*  [SR0402-TA]  228.22 56.77 180 top
R1106  4.7k  [SR0402-TA]  228.22 55.75 180 top
R1107  10k*  [SR0402-TA]  219.96 43.33 90 top
R1108  33  [SR0402-TA]  227.46 49.66 90 top
R1109  10k*  [SR0402-TA]  227.46 43.33 90 top
R1110  10k*  [SR0402-TA]  227.46 51.56 270 top
R1111  10k*  [SR0402-TA]  219.96 47.75 270 top
R1112  10k  [SR0402-TA]  219.96 56.77 180 top
R1113  20k  [SR0402-TA]  227.46 47.75 90 top
R1114  20k  [SR0402-TA]  228.98 53.97 270 top
R1115  0*  [SR0402-TA]  210.95 57.78 0 top
R1116  1k  [SR0402-TA]  210.95 56.64 180 top
R1117  1k  [SR0402-TA]  216.92 57.78 0 top
R1118  10k  [SR0402-TA]  209.04 57.78 180 top
R1119  1k  [SR0402-TA]  216.92 56.77 180 top
R1120  10k  [SR0402-TA]  211.84 52.07 180 top
R1201  1k  [SR0402-TA]  149.48 71.12 0 top
R1202  10k  [SR0402-TA]  137.51 65.4 90 top
R1203  4.7k*  [SR0402-TA]  139.23 65.4 270 top
R1204  2.49k  [SR0603B]  149.99 76.45 180 top
R1205  4.7k*  [SR0402-TA]  147.7 68.2 270 top
R1206  4.7k*  [SR0402-TA]  140.94 65.4 90 top
R1207  4.7k*  [SR0402-TA]  137.97 68.83 180 top
R1208  4.7k*  [SR0402-TA]  137.97 69.68 180 top
R1209  4.7k*  [SR0402-TA]  136.17 70.92 0 top
R1210  4.7k*  [SR0402-TA]  149.35 65.91 90 top
R1211  4.7k  [SR0402-TA]  153.29 69.09 180 top
R1212  4.7k  [SR0402-TA]  148.21 66.29 90 top
R1213  4.7k  [SR0402-TA]  148.84 68.2 270 top
R1214  4.7k*  [SR0402-TA]  151.38 69.09 180 top
R1215  0  [SR0402-TA]  145.57 68.2 90 top
R1216  1k  [SR0402-TA]  149.48 70.23 0 top
R1217  1k  [SR0402-TA]  149.48 72.9 0 top
R1218  1k  [SR0402-TA]  149.48 72.01 0 top
R1219  1M*  [SR0402-TA]  151.38 74.27 0 top
R1220  33  [SR0402-TA]  149.48 75.06 0 top
R1221  4.7k  [SR0402-TA]  147.07 66.04 90 top
R1222  1k  [SR0402-TA]  137.85 78.08 270 top
R1223  33  [SR0402-TA]  138.26 67.03 90 top
R1224  33  [SR0402-TA]  136.17 67.5 180 top
R1225  33  [SR0402-TA]  136.17 68.35 180 top
R1226  33  [SR0402-TA]  136.17 71.77 180 top
R1227  33  [SR0402-TA]  141.45 67.03 90 top
R1228  33  [SR0402-TA]  139.43 67.03 90 top
R1235  0  [SR0402-TA]  139.01 74.95 0 top
R1236  0  [SR0402-TA]  138.3 75.84 0 top
R1237  0*  [SR0402-TA]  136.17 64.92 0 top
R1238  0  [SR0402-TA]  138 63.52 90 top
R1239  1k  [SR0402-TA]  136.17 65.78 180 top
R1240  4.7k*  [SR0402-TA]  141.79 65.4 90 top
R1241  1k  [SR0402-TA]  140.08 65.4 270 top
R1242  1k  [SR0402-TA]  142.65 65.4 270 top
R1243  1k  [SR0402-TA]  136.17 70.06 180 top
R1244  1k  [SR0402-TA]  136.17 69.21 180 top
R1245  1k  [SR0402-TA]  135.74 78.82 180 top
R1246  1k*  [SR0402-TA]  135.74 77.93 0 top
R1247  1k  [SR0402-TA]  135.74 77.04 0 top
R1301  2.2  [SR0402-TB]  143.93 157.99 0 top
R1302  2.2  [SR0402-TB]  143.93 159.44 0 top
R1303  2.2  [SR0402-TB]  138.87 156.88 0 top
R1304  2.2  [SR0402-TB]  138.87 158.33 0 top
R1305  2.2  [SR0402-TB]  148.98 154.07 0 top
R1306  2.2  [SR0402-TB]  148.98 155.52 0 top
R1307  2.2  [SR0402-TB]  143.93 152.65 0 top
R1308  2.2  [SR0402-TB]  143.93 154.1 0 top
R1309  2.2  [SR0402-TB]  138.87 151.53 0 top
R1310  1M*  [SR0402-TA]  129.01 135.33 0 top
R1311  2.2  [SR0402-TB]  138.87 152.98 0 top
R1312  2.2  [SR0402-TB]  138.87 148.73 0 top
R1313  2.2  [SR0402-TB]  138.87 150.18 0 top
R1314  2.2  [SR0402-TB]  143.93 147.31 0 top
R1315  2.2  [SR0402-TB]  148.98 146.19 0 top
R1316  2.2  [SR0402-TB]  143.93 148.76 0 top
R1317  2.2  [SR0402-TB]  144.78 78.64 90 top
R1318  33  [SR0402-TA]  97.21 129.79 270 top
R1319  4.7k  [SR0402-TA]  117.53 131.57 0 top
R1320  33  [SR0402-TA]  98.07 129.79 270 top
R1321  33  [SR0402-TA]  98.92 129.79 270 top
R1322  33  [SR0402-TA]  99.78 129.79 270 top
R1323  33  [SR0402-TA]  100.63 129.79 270 top
R1324  33  [SR0402-TA]  101.51 130.89 270 top
R1325  4.7k  [SR0402-TA]  117.53 128.52 180 top
R1326  33  [SR0402-TA]  128.27 133.81 270 top
R1328  100k  [SR0402-TA]  122.99 132.59 0 top
R1329  0  [SR0402-TA]  117.53 130.56 0 top
R1330  0  [SR0402-TA]  124.38 130.56 0 top
R1331  4.7k  [SR0402-TA]  124.38 131.57 180 top
R1332  4.7k  [SR0402-TA]  124.38 128.52 180 top
R1333  33  [SR0402-TA]  124.38 129.54 0 top
R1334  0  [SR0402-TA]  117.53 129.54 0 top
R1335  2.2  [SR0402-TB]  131.7 159.77 0 top
R1336  2.2  [SR0402-TB]  131.7 158.32 0 top
R1337  2.2  [SR0402-TB]  131.7 162.36 0 top
R1338  2.2  [SR0402-TB]  131.7 160.91 0 top
R1339  2.2  [SR0402-TB]  127.87 162.41 90 top
R1340  2.2  [SR0402-TB]  128.78 162.41 90 top
R1341  2.2  [SR0402-TB]  124.52 161.04 90 top
R1342  2.2  [SR0402-TB]  125.43 161.04 90 top
R1343  2.2  [SR0402-TB]  121.57 162.51 90 top
R1344  2.2  [SR0402-TB]  122.48 162.51 90 top
R1345  2.2  [SR0402-TB]  118.32 162.51 90 top
R1346  2.2  [SR0402-TB]  119.23 162.51 90 top
R1347  2.2  [SR0402-TB]  115.07 162.51 90 top
R1348  2.2  [SR0402-TB]  115.98 162.51 90 top
R1349  2.2  [SR0402-TB]  111.82 162.51 90 top
R1350  2.2  [SR0402-TB]  112.73 162.51 90 top
R1351  4.7k*  [SR0402-TA]  124.58 134.12 90 top
R1352  4.7k*  [SR0402-TA]  123.23 134.12 90 top
R1353  4.7k  [SR0402-TA]  126.7 133.12 90 top
R1354  4.7k  [SR0402-TA]  125.68 133.12 90 top
R1355  4.7k  [SR0402-TA]  122.38 134.12 90 top
R1356  4.7k  [SR0402-TA]  127.84 129.23 90 top
R1357  4.7k  [SR0402-TA]  120.95 134.12 90 top
R1358  4.7k  [SR0402-TA]  126.82 129.23 90 top
R1359  4.7k  [SR0402-TA]  120.1 134.12 90 top
R1360  4.7k  [SR0402-TA]  118.67 134.12 90 top
R1361  4.7k  [SR0402-TA]  132.35 156.36 270 top
R1362  4.7k*  [SR0402-TA]  118.67 136.97 270 top
R1363  4.7k*  [SR0402-TA]  126.82 131.42 90 top
R1364  4.7k*  [SR0402-TA]  120.1 136.97 270 top
R1365  4.7k*  [SR0402-TA]  120.95 136.97 270 top
R1366  4.7k*  [SR0402-TA]  127.84 131.42 90 top
R1367  4.7k*  [SR0402-TA]  125.68 135.2 90 top
R1368  4.7k*  [SR0402-TA]  126.7 135.2 90 top
R1369  4.7k  [SR0402-TA]  123.23 136.97 270 top
R1370  4.7k  [SR0402-TA]  124.66 136.97 270 top
R1371  4.7k*  [SR0402-TA]  122.38 136.97 270 top
R1372  1k*  [SR0402-TA]  131.49 156.36 90 top
R1373  4.7k  [SR0402-TA]  112.57 157.94 0 top
R1374  4.7k  [SR0402-TA]  109.14 142.89 0 top
R1375  4.7k  [SR0402-TA]  109.14 149.22 180 top
R1376  4.7k  [SR0402-TA]  111.3 150.49 0 top
R1377  4.7k  [SR0402-TA]  111.3 149.22 0 top
R1378  4.7k  [SR0402-TA]  109.14 147.95 180 top
R1379  4.7k  [SR0402-TA]  111.3 147.95 0 top
R1380  4.7k  [SR0402-TA]  109.14 147.07 0 top
R1381  4.7k  [SR0402-TA]  111.3 146.68 0 top
R1382  2.49k  [SR0603B]  122.4 160.21 0 top
R1401  4.7k  [SR0402-TA]  109.14 150.49 0 top
R1402  33  [SR0402-TA]  98.17 151.74 270 top
R1403  1k*  [SR0402-TA]  106.43 146.23 180 top
R1405  10k  [SR0402-TA]  98.32 146.51 0 top
R1406  10k  [SR0402-TA]  98.7 145.24 270 top
R1407  10k  [SR0402-TA]  99.89 151.74 90 top
R1408  12k  [SR0402-TA]  100.74 151.74 270 top
R1501  200  [SR0402-TA]  188.47 181.99 270 top
R1502  200  [SR0402-TA]  189.53 181.99 270 top
R1503  200  [SR0402-TA]  191.64 181.99 270 top
R1504  200  [SR0402-TA]  190.58 181.99 270 top
R1505  200  [SR0402-TA]  195.88 181.99 270 top
R1506  200  [SR0402-TA]  194.82 181.99 270 top
R1507  200  [SR0402-TA]  193.76 181.99 270 top
R1508  200  [SR0402-TA]  192.7 181.99 270 top
R1509  75  [SR0805-TB]  144.63 195.43 270 top
R1510  75  [SR0805-TB]  161.15 194 90 top
R1511  75  [SR0805-TB]  170.18 191.85 180 top
R1512  75  [SR0805-TB]  208.03 193.67 90 top
R1601  4.7k  [SR0402-TA]  77.88 154.38 270 top
R1602  33  [SR0402-TA]  74.68 154.36 90 top
R1603  33  [SR0402-TA]  73.58 154.35 90 top
R1604  33  [SR0402-TA]  76.94 164.06 180 top
R1605  150*  [SR0805-TB]  75.82 167.61 180 top
R1606  240  [SR0402-TA]  75.01 166.17 180 top
R1607  240  [SR0402-TA]  76.94 166.14 180 top
R1608  33  [SR0402-TA]  75.01 164.06 0 top
R1609  15k  [SR0402-TA]  75.69 154.36 270 top
R1610  4.7k*  [SR0402-TA]  76.71 154.36 90 top
R1611  4.7k  [SR0402-TA]  72.55 154.34 90 top
R1612  100*  [SR0402-TA]  80.06 167.6 180 top
R1613  100*  [SR0402-TA]  86.21 167.22 180 top
R1614  33  [SR0402-TA]  192.99 155.02 180 top
R1615  100  [SR0402-TA]  192.99 158.06 0 top
R1616  1k*  [SR0402-TA]  93.88 145.54 0 top
R1617  33  [SR0402-TA]  84.56 162.23 90 top
R1618  33  [SR0402-TA]  83.41 162.23 90 top
R1619  10k  [SR0402-TA]  82.83 163.52 180 top
R1620  45.3k  [SR0603-TB]  84.53 164.34 270 top
R1621  45.3k  [SR0603-TB]  85.74 164.34 270 top
R1622  10k  [SR0402-TA]  87.38 163.88 90 top
R1623  33  [SR0402-TA]  85.7 162.23 90 top
R1624  33  [SR0402-TA]  87.38 162.25 90 top
R1625  33  [SR0402-TA]  80.9 152.65 0 top
R1626  1k  [SR0402-TA]  82.68 152.65 0 top
R1627  10k  [SR0402-TA]  84.58 152.65 0 top
R1628  0  [SR0402-TA]  82.3 162.25 90 top
R1629  200  [SR0402-TA]  197.99 181.99 270 top
R1630  200  [SR0402-TA]  196.93 181.99 270 top
R1631  75  [SR0805-TB]  230.28 192.48 90 top
R1632  0  [SR0402-TA]  134.78 187.19 225 top
R1633  0  [SR0402-TA]  88.9 170.94 180 top
R1634  0  [SR0402-TA]  236.86 184.61 0 top
R1635  0  [SR0402-TA]  127.51 201.04 180 top
R1636  0  [SR0402-TA]  133.2 190.22 180 top
R1637  0  [SR0402-TA]  73.51 170.14 90 top
R1638  0  [SR0402-TA]  86.67 195.47 180 top
R1639  0  [SR0402-TA]  30.86 190.88 315 top
R1640  33  [SR0402-TA]  94.87 159.77 90 top
R1641  30k  [SR0402-TA]  89.41 164.46 270 top
R1642  4.7k  [SR0402-TA]  192.99 152.86 0 top
R1643  1k  [SR0402-TA]  192.99 151.71 180 top
R1644  10k  [SR0402-TA]  192.99 154 180 top
R1645  4.7k*  [SR0402-TA]  179.38 152.93 180 top
R1646  4.7k*  [SR0402-TA]  192.99 156.03 0 top
R1647  4.7k  [SR0402-TA]  94.87 162.31 270 top
R1648  4.7k  [SR0402-TA]  89.54 154.94 90 top
R1649  33  [SR0603-TB]  89.92 167.13 270 top
R1650  33  [SR0603-TB]  91.82 167.13 270 top
R1651  4.7k  [SR0402-TA]  86.33 152.6 180 top
R1652  4.7k  [SR0402-TA]  79.12 152.65 0 top
R1701  1k  [SR0402-TA]  70.99 157.99 270 top
R1702  4.7k  [SR0402-TA]  70.99 160.27 270 top
R1703  0*  [SR0402-TA]  72.34 175.77 180 top
R1704  240  [SR0402-TA]  81.27 183.37 90 top
R1705  240  [SR0402-TA]  81.27 188.7 90 top
R1706  240  [SR0402-TA]  81.34 173.64 90 top
R1707  240  [SR0402-TA]  81.26 179.09 90 top
R1708  1k  [SR0402-TA]  49.28 159.14 180 top
R1709  4.7k  [SR0402-TA]  51.56 159.27 180 top
R1710  0*  [SR0402-TA]  52.94 175.79 180 top
R1711  1k  [SR0402-TA]  42.67 159.27 180 top
R1712  4.7k  [SR0402-TA]  44.96 159.27 180 top
R1713  0*  [SR0402-TA]  34.61 175.89 0 top
R1714  1k  [SR0402-TA]  63.93 157.99 270 top
R1715  4.7k  [SR0402-TA]  63.93 160.27 270 top
R1716  0*  [SR0402-TA]  62.79 175.77 180 top
R1801  10k*  [SR0402-TA]  29.21 158.75 270 top
R1802  10k  [SR0402-TA]  31.37 158.75 270 top
R1803  10k*  [SR0402-TA]  33.78 163.7 90 top
R1804  10k  [SR0402-TA]  32.77 161.92 270 top
R1805  1k  [SR0402-TA]  27.05 161.54 0 top
R1806  1k  [SR0402-TA]  27.05 162.69 180 top
R1807  33  [SR0402-TA]  54.86 147.58 180 top
R1808  33  [SR0402-TA]  54.86 148.72 180 top
R1809  33  [SR0402-TA]  47.44 142.71 90 top
R1810  4.7k  [SR0402-TA]  47.44 140.53 90 top
R1811  10k  [SR0402-TA]  49.98 140.53 90 top
R1812  10k  [SR0402-TA]  57.15 149.61 180 top
R1813  10k  [SR0402-TA]  57.15 150.49 180 top
R1814  10k  [SR0402-TA]  53.79 140.53 90 top
R1815  10k  [SR0402-TA]  57.19 144.67 180 top
R1816  10k  [SR0402-TA]  52.52 140.53 90 top
R1817  10k  [SR0402-TA]  51.25 140.53 90 top
R1818  10k  [SR0402-TA]  48.71 140.53 90 top
R1819  10k  [SR0402-TA]  57.19 145.63 180 top
R1820  20k  [SR0402-TA]  57.15 146.56 0 top
R1821  1k  [SR0402-TA]  24.77 161.54 180 top
R1822  1k  [SR0402-TA]  24.77 162.69 0 top
R1823  33  [SR0402-TA]  28.19 158.75 270 top
R1824  33  [SR0402-TA]  32.77 163.7 90 top
R1825  10  [SR0402-TA]  52.52 142.73 90 top
R1826  10  [SR0402-TA]  51.25 142.71 90 top
R1827  10  [SR0402-TA]  48.71 142.71 90 top
R1828  10  [SR0402-TA]  54.86 145.61 180 top
R1829  10  [SR0402-TA]  54.86 144.65 180 top
R1830  10  [SR0402-TA]  53.79 142.73 90 top
R1831  10  [SR0402-TA]  54.86 150.49 180 top
R1832  10  [SR0402-TA]  54.86 149.61 180 top
R1833  10k  [SR0402-TA]  57.15 148.46 0 top
R1901  10k*  [SR0402-TA]  114.72 22.74 0 top
R1902  33  [SR0402-TA]  128.45 21.3 90 top
R1903  33  [SR0402-TA]  128.68 23.32 180 top
R1904  33  [SR0402-TA]  123.35 21.47 270 top
R1905  33  [SR0402-TA]  120.23 21.48 270 top
R1906  33  [SR0402-TA]  120.23 23.76 270 top
R1907  47k  [SR0402-TA]  130.3 23.35 180 top
R1908  47k  [SR0402-TA]  129.34 21.3 270 top
R1909  47k  [SR0402-TA]  121.08 23.76 90 top
R1910  47k  [SR0402-TA]  121.08 21.48 90 top
R1911  47k  [SR0402-TA]  122.34 21.47 90 top
R1912  100  [SR0402-TA]  114.72 20.64 0 top
R1913  100  [SR0402-TA]  131.81 7.67 0 top
R1914  4.7k  [SR0402-TA]  131.81 8.53 180 top
R1915  1k  [SR0402-TA]  137.49 4.8 0 top
R1916  2k  [SR0402-TA]  137.85 6.39 90 top
R1917  10k  [SR0402-TA]  132.17 19.18 0 top
R1918  10k  [SR0402-TA]  114.72 19.63 180 top
R2001  33*  [SR0402-TA]  57.53 46.41 180 top
R2002  33*  [SR0402-TA]  69.47 46.13 180 top
R2003  33*  [SR0402-TA]  69.47 44.42 0 top
R2004  33*  [SR0402-TA]  57.53 47.68 0 top
R2005  6.04k*  [SR0402-TA]  145.03 39.75 0 top
R2006  4.7k*  [SR0402-TA]  131.32 47.35 0 top
R2007  0*  [SR0402-TA]  145.03 38.73 180 top
R2008  10k*  [SR0402-TA]  131.83 39.5 180 top
R2009  1M*  [SR0402-TA]  131.83 37.59 180 top
R2010  1M*  [SR0402-TA]  145.29 37.21 270 top
R2011  0*  [SR0402-TA]  143.76 36.83 0 top
R2012  0*  [SR0402-TA]  143.76 37.72 0 top
R2013  0*  [SR0402-TA]  125.63 35.66 270 top
R2014  0*  [SR0402-TA]  122.5 37.03 270 top
R2015  0*  [SR0402-TA]  121.01 37.03 270 top
R2016  0*  [SR0402-TA]  124.16 35.66 270 top
R2017  0*  [SR0402-TA]  125.63 34.85 90 top
R2018  0*  [SR0402-TA]  122.5 36.22 90 top
R2019  0*  [SR0402-TA]  121.01 36.22 90 top
R2020  0*  [SR0402-TA]  124.16 34.85 90 top
R2021  0  [SR0402-TA]  119.46 37.21 270 top
R2022  0  [SR0402-TA]  118.44 37.21 270 top
R2023  0*  [SR0402-TA]  119.46 36.4 90 top
R2024  0*  [SR0402-TA]  118.44 36.4 90 top
R2025  4.7k  [SR0402-TA]  132.97 64.52 90 top
R2026  33  [SR0402-TA]  132.72 76.75 270 top
R2027  33  [SR0402-TA]  131.83 76.75 270 top
R2028  33  [SR0402-TA]  133.84 64.5 270 top
R2029  33  [SR0402-TA]  134.73 64.5 270 top
R2030  4.7k  [SR0402-TA]  136.14 63.91 0 top
R2031  4.7k  [SR0402-TA]  136.17 62.89 0 top
R2032  4.7k*  [SR0402-TA]  131.45 44.32 180 top
R2033  0*  [SR0402-TA]  131.32 50.29 180 top
R2034  10k*  [SR0402-TA]  69.47 46.99 180 top
R2035  10k*  [SR0402-TA]  57.53 45.14 0 top
R2036  10k*  [SR0402-TA]  71.22 45.47 90 top
R2037  1k*  [SR0402-TA]  69.47 45.28 180 top
R2038  10k*  [SR0402-TA]  131.49 45.61 0 top
R2101  6.2k  [SR0402-TA]  97.17 43.75 0 top
R2102  10k  [SR0402-TA]  97.17 44.77 0 top
R2103  10k  [SR0402-TA]  97.17 45.78 0 top
R2107  0  [SR0402-TA]  107.88 40.51 180 top
